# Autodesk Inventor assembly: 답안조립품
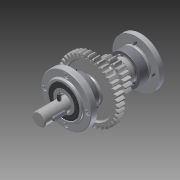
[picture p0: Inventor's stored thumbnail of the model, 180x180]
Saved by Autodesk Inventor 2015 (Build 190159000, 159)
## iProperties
Created: 2016-01
Part Number: 답안조립품
Document SubType Name: Assembly
Designer: Administrator
Author: Administrator
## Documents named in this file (16)
- C:\Users\Administrator\Desktop\460105V1018\답안조립품.iam
- C:\Users\Administrator\Desktop\460105V1018\본체.ipt
- C:\Users\Administrator\Desktop\460105V1018\뒤커버.ipt
- C:\Users\Administrator\Desktop\460105V1018\베어링 6203.ipt
- C:\Users\Administrator\Desktop\460105V1018\볼트 M3 x 8.ipt
- C:\Users\Administrator\Desktop\460105V1018\볼트 M3 x 10.ipt
- C:\Users\Administrator\Desktop\460105V1018\앞커버.ipt
- C:\Users\Administrator\Desktop\460105V1018\오일씰 28 40 8.ipt
- C:\Users\Administrator\Desktop\460105V1018\부시1.ipt
- C:\Users\Administrator\Desktop\460105V1018\스퍼기어.ipt
- C:\Users\Administrator\Desktop\460105V1018\축.ipt
- C:\Users\Administrator\Desktop\460105V1018\키 - 6 x 6 x 22.ipt
- C:\Users\Administrator\Desktop\460105V1018\V-벨트풀리.ipt
- C:\Users\Administrator\Desktop\460105V1018\멈춤나사 - M4x10.ipt
- C:\Users\Administrator\Desktop\460105V1018\부시2.ipt
- C:\Users\Administrator\Desktop\460105V1018\키 - 5 x 5 x 18.ipt
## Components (9 placed, 3 different names)
1. V-벨트풀리:1 — 각도:6, 각도:7
2. ISO 4762 M3 x 8:1 — 각도:1
3. ISO 4762 M3 x 8:2
4. ISO 4762 M3 x 8:3
5. ISO 4762 M3 x 8:4
6. ISO 4762 M3 x 10:1 — 각도:2
7. ISO 4762 M3 x 10:2
8. ISO 4762 M3 x 10:3
9. ISO 4762 M3 x 10:4
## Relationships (4: Angle 4)
- 각도:1 [Angle]: ISO 4762 M3 x 8:1
- 각도:2 [Angle]: ISO 4762 M3 x 10:1
- 각도:6 [Angle]: V-벨트풀리:1
- 각도:7 [Angle]: V-벨트풀리:1
